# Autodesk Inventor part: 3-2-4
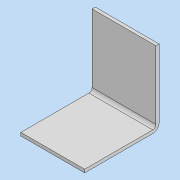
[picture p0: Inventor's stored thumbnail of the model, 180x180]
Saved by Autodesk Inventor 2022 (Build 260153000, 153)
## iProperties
Created: 2021-07
Part Number: 3-2-4
Material: 一般
Document SubType Name: Modeling
Designer: DesignLab
Density: 1 g/cm^3
Appearance: 既定
Author: DesignLab
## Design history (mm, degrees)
sketch "スケッチ1"
  geometry: L1 (0, 0)-(70, 0); L2 (70, 0)-(70, 70); L3 (70, 70)-(0, 70); L4 (0, 70)-(0, 0)
  constraints: 8 end point, 2 parallel, 1 horizontal, 1 perpendicular
  dimensions: "d0" = 70 distance of L3.end L2.end; "d1" = 70 distance of L2.end L1.end
extrude "押し出し1" new body sketch "スケッチ1" stored distance "d2" = 60; taper "d3" = 0 deg
fillet "フィレット1" dims "d4" = 6
feature "シェル1" dims "d5" = 3
node "ソリッド1"
